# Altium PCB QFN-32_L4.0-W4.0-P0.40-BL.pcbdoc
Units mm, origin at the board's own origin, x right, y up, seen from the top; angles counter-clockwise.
Board outline 17.85 x 17.5 mm, 2 copper layers (Top Layer, Bottom Layer); 1 components, 0 nets, 33 pads, 9 vias.
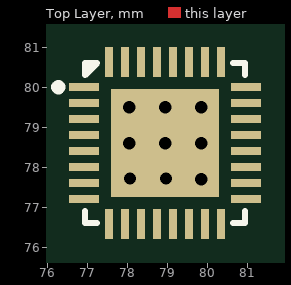
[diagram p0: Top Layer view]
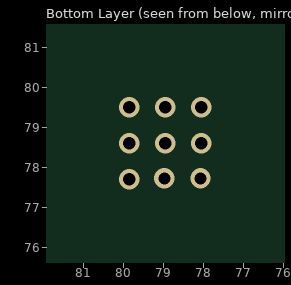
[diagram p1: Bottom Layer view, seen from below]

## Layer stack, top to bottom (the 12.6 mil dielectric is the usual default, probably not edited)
Top Layer: signal copper (thickness not stored)
Dielectric: dielectric 0.32, FR-4, Dk 4.8
Bottom Layer: signal copper (thickness not stored)

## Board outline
87.698,69.85 69.85,69.85 69.85,87.35 87.698,87.35

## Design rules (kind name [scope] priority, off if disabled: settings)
BoardOutlineClearance safeClearance [All] p0: genericclearance=0.254 ignorepadtopadclearanceinfootprint=FALSE except(0: Arc-SplitContinuation Track-SplitContinuation SMDPad-SplitContinuation THPad-SplitContinuation Via-SplitContinuation Fill-SplitContinuation Poly-SplitContinuation Region-SplitContinuation Text-SplitContinuation; 0.152: Track-CutoutEdge SMDPad-CutoutEdge THPad-CutoutEdge Via-CutoutEdge Fill-CutoutEdge Region-CutoutEdge; 0.3: Track-OutlineEdge SMDPad-OutlineEdge THPad-OutlineEdge Via-OutlineEdge Fill-OutlineEdge Region-OutlineEdge Poly-OutlineEdge Text-OutlineEdge)
Clearance safeClearance [All] p1: gap=0.178 ignorepadtopadclearanceinfootprint=FALSE except(0.152: Track-Track Track-SMDPad SMDPad-SMDPad Track-THPad SMDPad-THPad THPad-THPad Track-Via SMDPad-Via THPad-Via Via-Via Track-Fill SMDPad-Fill THPad-Fill Via-Fill Fill-Fill Track-Region SMDPad-Region THPad-Region Via-Region Fill-Region Region-Region Track-Poly SMDPad-Poly THPad-Poly Via-Poly Fill-Poly Region-Poly Poly-Poly Track-Text SMDPad-Text THPad-Text Via-Text Fill-Text Region-Text Poly-Text Text-Text; 0.175: Track-Hole SMDPad-Hole THPad-Hole Via-Hole Fill-Hole Region-Hole Poly-Hole Text-Hole Sheet-Hole; 0.3: Track-Sheet SMDPad-Sheet THPad-Sheet Via-Sheet Fill-Sheet Region-Sheet Poly-Sheet Text-Sheet)
DiffPairsRouting differentialPair [All] p1: maxuncoupledlength=10 minlimit=6 maxlimit=6 mostfreqgap=6 toplayer_minwidth=5 toplayer_prefwidth=10 toplayer_maxwidth=100 bottomlayer_minwidth=5 bottomlayer_prefwidth=10 bottomlayer_maxwidth=100
PasteMaskExpansion pasteMaskExpansion [All] p1: expansion=0
PlaneConnect innerPlane [All] p1: planeconnectstyle=Relief reliefexpansion=0.508 reliefentries=4 reliefconductorwidth=0.254 reliefairgap=0.254
PolygonConnect copperRegion [All] p1: connectstyle=Relief reliefentries=4 reliefconductorwidth=10 polygonreliefangle="90 Angle" airgapwidth=10
RoutingVias viaSize [All] p1: viastyle="Through Hole" holewidth=12.0078 minholewidth=11.811 maxholewidth=236.2204 width=24.0158 minwidth=19.685 maxwidth=393.7008
SolderMaskExpansion solderMaskExpansion [All] p1: useseparateexpansions=TRUE expansion=2 expansionbottom=2
Width trackWidth [All] p1: maxlimit=100 minlimit=5 preferedwidth=10

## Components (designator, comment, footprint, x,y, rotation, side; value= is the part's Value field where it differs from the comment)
? "QFN-32_L4.0-W4.0-P0.40-BL-EP2.7" QFN-32_L4.0-W4.0-P0.40-BL-EP2.7 78.948,78.6 r0 top

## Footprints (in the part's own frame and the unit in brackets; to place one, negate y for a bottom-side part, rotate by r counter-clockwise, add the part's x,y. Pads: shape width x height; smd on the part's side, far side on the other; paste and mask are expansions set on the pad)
QFN-32_L4.0-W4.0-P0.40-BL-EP2.7 [mm]
  rect 0.75x0.2 smd: 1(-2.025,1.4) 2(-2.025,1) 3(-2.025,0.6) 4(-2.025,0.2) 5(-2.025,-0.2) 6(-2.025,-0.6) 7(-2.025,-1) 8(-2.025,-1.4) 17(2.025,-1.4) 18(2.025,-1) 19(2.025,-0.6) 20(2.025,-0.2) 21(2.025,0.2) 22(2.025,0.6) 23(2.025,1) 24(2.025,1.4)
  rect 0.2x0.75 smd: 9(-1.4,-2.025) 10(-1,-2.025) 11(-0.6,-2.025) 12(-0.2,-2.025) 13(0.2,-2.025) 14(0.6,-2.025) 15(1,-2.025) 16(1.4,-2.025) 25(1.4,2.025) 26(1,2.025) 27(0.6,2.025) 28(0.2,2.025) 29(-0.2,2.025) 30(-0.6,2.025) 31(-1,2.025) 32(-1.4,2.025)
  rect 2.7x2.7 smd: 33(0,0)
  silkscreen extent -2.75,-2 2,2

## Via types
v1: diameter 0.508, hole 0.305, Top Layer to Bottom Layer, 9 vias

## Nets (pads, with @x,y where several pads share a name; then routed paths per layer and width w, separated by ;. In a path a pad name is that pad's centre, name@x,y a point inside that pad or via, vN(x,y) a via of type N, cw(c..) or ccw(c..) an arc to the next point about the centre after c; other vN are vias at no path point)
pads on no net: ?.1 ?.2 ?.3 ?.4 ?.5 ?.6 ?.7 ?.8 ?.9 ?.10 ?.11 ?.12 ?.13 ?.14 ?.15 ?.16 ?.17 ?.18 ?.19 ?.20 ?.21 ?.22 ?.23 ?.24 ?.25 ?.26 ?.27 ?.28 ?.29 ?.30 ?.31 ?.32 ?.33
copper on no net:
  other v1: 79.848,77.7 78.068,77.72 78.968,77.72 78.048,78.6 78.948,78.6 79.848,78.6 78.048,79.5 78.948,79.5 79.848,79.5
